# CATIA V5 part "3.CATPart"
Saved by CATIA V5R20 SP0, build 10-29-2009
Part number: 3
Bounding box of the stored display mesh (mm): x 0 to 78, y -42.078 to 42.078, z -32 to 32
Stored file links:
  E:\Ehsan\Amoozesh\CATIA\CATIA Course\Advanced\Videos\Session-21\3.CATPart
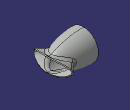
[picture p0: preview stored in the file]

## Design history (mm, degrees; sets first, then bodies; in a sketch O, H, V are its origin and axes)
Set1
  Revol1: Element1 Sketch5, Angle1 180
  Sketch1 on xy-plane, origin (0, 0, 0), H (1, 0, 0), V (0, 1, 0)
    arc A1 centre (0.1381, 101.4979) radius 90 from (25, 15) to (80, 60) ccw
    point P2 (25, 15)
    point P3 (80, 60)
    reference projected line E1 (0, 0) -> (70, 0) from Sketch5.A1
    radius A1 = 90
    distance P3 E1 = 60
    distance P2 H = 15
    distance P3 V = 80
    distance P2 V = 25
  Plane1: type OffsetPt, RefPlane yz-plane, RefPoint Sketch1.P3
  Plane2: type OffsetPt, RefPlane yz-plane, RefPoint Sketch1.P2
  Sketch2 on Plane1, origin (80, 0, 0), H (0, 1, 0), V (0, 0, 1)
    ellipse A1 centre (0, 0) semi-axes 60, 15 rotation 0
    point P1 (60, 0)
    "Radius" A1 = 60
    "Radius" A1 = 15
    coincidence: P1 H, A1 P1
  Sketch3 on Plane2, origin (25, 0, 0), H (0, 1, 0), V (0, 0, 1)
    ellipse A1 centre (0, 0) semi-axes 15, 5 rotation 0
    point P1 (15, 0)
    reference projected point E1 (15, 0) from Sketch1.P2
    "Radius" A1 = 5
    coincidence: P1 H, A1 P1, A1 E1
  Symmetry1: Reference zx-plane, ToTransfor Sketch1
  Loft1: Sections (Sketch2; Sketch3), Guides (Sketch1; Symmetry1)
  Split1: ToCut Loft1, Cutting zx-plane
  Fillet1: type BiTangent, Element1 Revol1, Element2 Split1, Radius 10
  Sketch4 on xy-plane, origin (0, 0, 0), H (1, 0, 0), V (0, 1, 0)
    arc A1 centre (0, 0) radius 78 from (78, 0) to (55.9138, 54.3842) ccw
    point P1 (78, 0)
    radius A1 = 78
    coincidence: P1 H
  Extrude1: Lim1 20, Lim2 20, Element1 Sketch4
  Split2: ToCut Fillet1, Cutting Extrude1
  Symmetry2: Reference zx-plane, ToTransfor Split2
  Join1: Elements (Split2; Symmetry2)
Body1 (main body)
  Sketch5 on zx-plane, origin (0, 0, 0), H (-1, 0, 0), V (0, 0, 1)
    construction line L1 (76.506, 30) -> (0, 30)
    point P2 (0, 30)
    arc A1 centre (0, -130) radius 160 from (0, 30) to (-70, 13.8749) ccw
    point P4 (-70, 13.8749)
    axis line L2 (-99.4578, 0) -> (121.5595, 0)
    point P5 (-99.4578, 0)
    distance P4 V = 70
    radius A1 = 160
    distance H L1 = 30
    coincidence: P2 V, P5 H
    horizontal: L1 H, L2 H
    tangency: A1 L1
  ThickSurface1: Surface Join1, TopOffset 2, BotOffset 0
